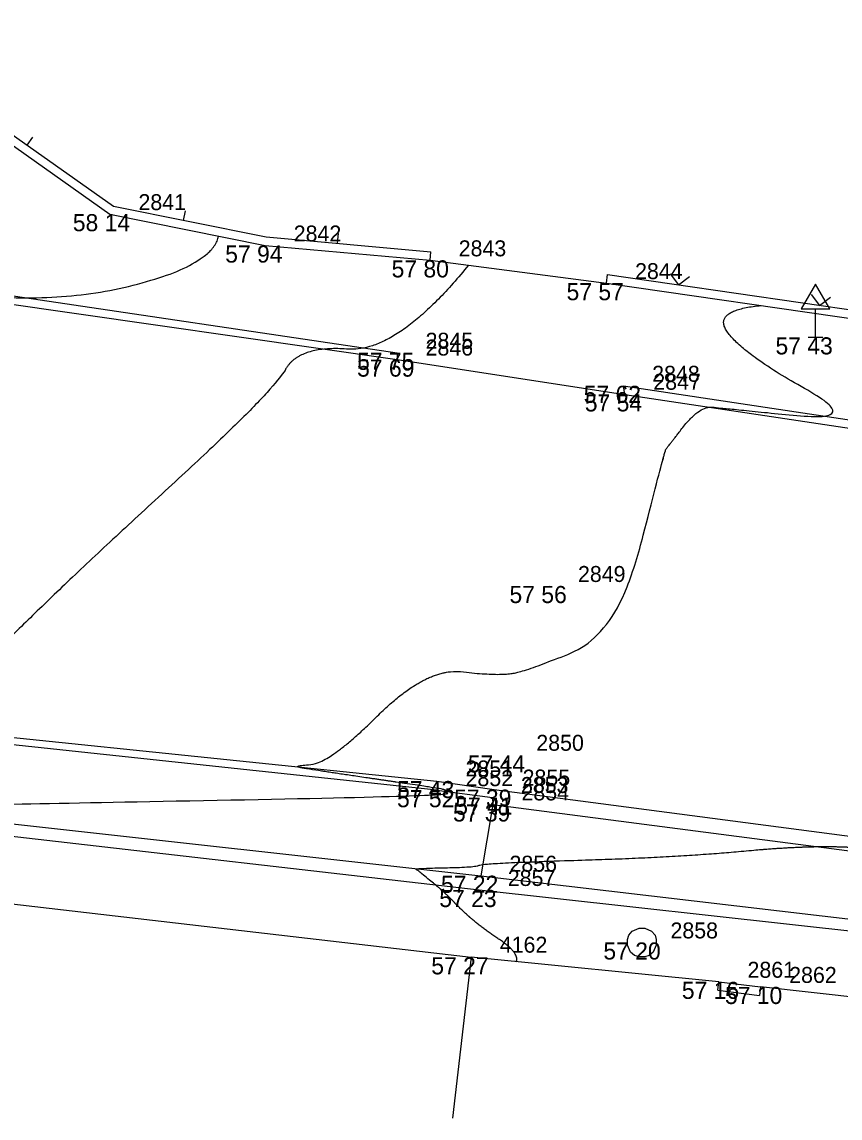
# Model space of a CAD drawing. Extents: x -704017 to -701500, y -1008977 to -1008450.
# Drawn here: x -702493.14 to -702478.81, y -1008778.35 to -1008759.13 of the extents above; entities that cross this region are included whole.
import ezdxf

# ---------------------------------------------------------------- set-up
doc = ezdxf.new("R2010")
doc.units = 0
for name, color, linetype in [('Z_body', 7, 'Continuous'), ('Z_body_cisla', 7, 'Continuous'), ('Z_body_vysky', 7, 'Continuous'), ('Z_budovy', 7, 'Continuous'), ('Z_chodnik', 7, 'Continuous'), ('Z_dopravni_znaceni', 7, 'Continuous'), ('Z_komunikace', 7, 'Continuous'), ('Z_obruby', 7, 'Continuous'), ('Z_oploceni', 7, 'Continuous'), ('Z_rozhrani_ploch', 7, 'Continuous'), ('Z_site_znaky_kanalizace', 7, 'Continuous'), ('Z_vrstevnice_hlavni', 7, 'Continuous'), ('Z_vrstevnice_vedlejsi', 7, 'Continuous'), ('Z_vstupy', 7, 'Continuous')]:
    doc.layers.add(name, color=color, linetype=linetype)

# ---------------------------------------------------------------- blocks, each defined once
blk = doc.blocks.new('POINT_DISPLAY')
blk.add_line((0, 0), (0, 0))
blk = doc.blocks.new('Z210')
blk.add_line((0, 0), (0, 0.17))
blk = doc.blocks.new('Z212')
for p, q in [((-0.17, 0.17), (0, 0)), ((0, 0), (0.17, 0.17))]:
    blk.add_line(p, q)
blk = doc.blocks.new('Z527')
for p, q in [((0, 0.93), (-0.25, 0.5)), ((0.25, 0.5), (0, 0.93)), ((-0.25, 0.5), (0.25, 0.5)), ((0, 0), (0, 0.5)), ((-0.13, 0), (0.13, 0))]:
    blk.add_line(p, q)
blk = doc.blocks.new('Z620')
for p, q in [((-0.23, 0.13), (-0.17, 0.2)), ((-0.17, 0.2), (-0.05, 0.25)), ((-0.05, 0.25), (0.05, 0.25)), ((0.05, 0.25), (0.17, 0.2)), ((0.17, 0.2), (0.23, 0.13)), ((-0.25, 0.05), (-0.23, 0.13)), ((-0.25, -0.05), (-0.25, 0.05)), ((0.23, 0.13), (0.25, 0.05)), ((0.25, 0.05), (0.25, -0.05)), ((-0.2, -0.17), (-0.25, -0.05)), ((-0.13, -0.23), (-0.2, -0.17)), ((0.2, -0.17), (0.13, -0.23)), ((0.25, -0.05), (0.2, -0.17)), ((-0.05, -0.25), (-0.13, -0.23)), ((0.05, -0.25), (-0.05, -0.25)), ((0.13, -0.23), (0.05, -0.25))]:
    blk.add_line(p, q)

msp = doc.modelspace()

# ---------------------------------------------------------------- linework, layer by layer
at = {"layer": 'Z_budovy'}
for p, q in [((-702495.22, -1008774.37), (-702485.27, -1008775.53)), ((-702485.27, -1008775.53), (-702485.6, -1008778.35))]:
    msp.add_line(p, q, dxfattribs=at)
at = {"layer": 'Z_chodnik'}
for p, q in [((-702495.54, -1008773.15), (-702485.13, -1008774.35)), ((-702485.13, -1008774.35), (-702477.28, -1008775.22))]:
    msp.add_line(p, q, dxfattribs=at)
at = {"layer": 'Z_komunikace'}
for p, q in [((-702495.43, -1008763.78), (-702486.57, -1008765.05)), ((-702486.57, -1008765.05), (-702482.58, -1008765.66)), ((-702482.58, -1008765.66), (-702468.75, -1008767.75)), ((-702495.38, -1008771.46), (-702485.87, -1008772.44)), ((-702485.87, -1008772.44), (-702484.87, -1008772.59)), ((-702484.87, -1008772.59), (-702477.01, -1008773.62))]:
    msp.add_line(p, q, dxfattribs=at)
at = {"layer": 'Z_obruby'}
for p, q in [((-702495.41, -1008763.62), (-702486.57, -1008764.93)), ((-702486.57, -1008764.93), (-702486.57, -1008765.05)), ((-702482.58, -1008765.66), (-702482.6, -1008765.51)), ((-702482.6, -1008765.51), (-702468.85, -1008767.59)), ((-702485.87, -1008772.6), (-702495.39, -1008771.58)), ((-702485.87, -1008772.6), (-702484.9, -1008772.73)), ((-702484.9, -1008772.73), (-702484.89, -1008772.85)), ((-702484.89, -1008772.85), (-702477.05, -1008773.87))]:
    msp.add_line(p, q, dxfattribs=at)
at = {"layer": 'Z_oploceni'}
for p, q in [((-702496.11, -1008759.13), (-702491.54, -1008762.36)), ((-702496.2, -1008759.25), (-702491.6, -1008762.5)), ((-702491.54, -1008762.36), (-702488.86, -1008762.9)), ((-702491.6, -1008762.5), (-702488.88, -1008763.05)), ((-702488.86, -1008762.9), (-702485.98, -1008763.16)), ((-702488.88, -1008763.05), (-702485.99, -1008763.31)), ((-702485.99, -1008763.31), (-702485.98, -1008763.16)), ((-702482.9, -1008763.71), (-702482.88, -1008763.56)), ((-702482.88, -1008763.56), (-702468.55, -1008765.63)), ((-702482.9, -1008763.71), (-702468.57, -1008765.78)), ((-702480.95, -1008776.11), (-702480.93, -1008775.96)), ((-702480.95, -1008776.11), (-702480.22, -1008776.2)), ((-702480.93, -1008775.96), (-702480.2, -1008776.05)), ((-702480.2, -1008776.05), (-702480.22, -1008776.2))]:
    msp.add_line(p, q, dxfattribs=at)
at = {"layer": 'Z_rozhrani_ploch'}
for p, q in [((-702495.54, -1008772.94), (-702485.1, -1008774.1)), ((-702484.89, -1008772.85), (-702485.1, -1008774.1)), ((-702485.1, -1008774.1), (-702477.22, -1008775.03))]:
    msp.add_line(p, q, dxfattribs=at)
at = {"layer": 'Z_vrstevnice_hlavni'}
msp.add_open_spline([(-702510.173, -1008772.658), (-702510.714, -1008772.203), (-702511.484, -1008771.252), (-702511.319, -1008771.123), (-702511.199, -1008771.066), (-702508.725, -1008770.905), (-702508.579, -1008770.878), (-702507.701, -1008770.748), (-702507.528, -1008770.584), (-702505.643, -1008770.573), (-702505.563, -1008770.58), (-702505.541, -1008770.602), (-702504.772, -1008770.664), (-702502.568, -1008770.251), (-702502.295, -1008770.203), (-702501.897, -1008770.153), (-702498.702, -1008767.51), (-702496.853, -1008766.543), (-702495.43, -1008763.78), (-702492.386, -1008764.068), (-702489.794, -1008763.372), (-702489.696, -1008762.885)], degree=2, dxfattribs=at)
at = {"layer": 'Z_vrstevnice_vedlejsi'}
for points in [[(-702485.318, -1008763.397), (-702486.57, -1008764.93), (-702488.285, -1008764.804), (-702488.762, -1008765.638), (-702492.37, -1008768.95), (-702494.464, -1008771.032), (-702495.307, -1008771.087), (-702496.276, -1008771.119), (-702497.81, -1008771.23)], [(-702493.746, -1008774.542), (-702493.918, -1008774.367), (-702495.54, -1008773.15), (-702495.838, -1008772.906), (-702495.627, -1008772.88), (-702495.54, -1008772.888), (-702495.534, -1008772.883), (-702492.317, -1008772.827), (-702485.819, -1008772.7), (-702485.719, -1008772.638), (-702485.694, -1008772.624), (-702485.716, -1008772.598), (-702485.87, -1008772.564), (-702488.091, -1008772.239), (-702488.43, -1008772.176), (-702487.75, -1008772.132), (-702486.058, -1008770.45), (-702484.809, -1008770.598), (-702484.265, -1008770.505), (-702482.684, -1008769.832), (-702481.884, -1008766.655), (-702481.829, -1008766.582), (-702481.263, -1008765.859), (-702480.808, -1008765.909), (-702478.369, -1008766.15), (-702480.478, -1008764.973), (-702481.07, -1008764.185), (-702480.189, -1008764.102)], [(-702484.481, -1008775.608), (-702484.416, -1008775.456), (-702485.2, -1008774.94), (-702485.781, -1008774.351), (-702485.901, -1008774.261), (-702486.219, -1008773.998), (-702486.26, -1008773.971), (-702485.177, -1008773.95), (-702485.063, -1008773.879), (-702481.636, -1008773.775), (-702479.402, -1008773.564), (-702478.013, -1008773.629), (-702478.401, -1008773.484), (-702478.397, -1008773.438), (-702478.049, -1008773.398), (-702477.618, -1008773.214), (-702477.532, -1008772.874), (-702477.136, -1008772.347), (-702473.031, -1008767.103), (-702469.736, -1008767.465), (-702469.555, -1008767.483), (-702469.889, -1008767.297), (-702470.89, -1008765.537), (-702470.506, -1008765.5)]]:
    msp.add_open_spline(points, degree=2, dxfattribs=at)
at = {"layer": 'Z_vstupy'}
for p, q in [((-702485.99, -1008763.31), (-702482.9, -1008763.71)), ((-702480.93, -1008775.96), (-702485.27, -1008775.53)), ((-702477.45, -1008776.36), (-702480.2, -1008776.05))]:
    msp.add_line(p, q, dxfattribs=at)

# ---------------------------------------------------------------- block references
at = {"layer": 'Z_body'}
for p in [(-702491.6, -1008762.5), (-702488.88, -1008763.05), (-702485.99, -1008763.31), (-702482.9, -1008763.71), (-702479.24, -1008764.66), (-702486.57, -1008764.93), (-702486.57, -1008765.05), (-702482.6, -1008765.51), (-702482.58, -1008765.66), (-702483.9, -1008769.02), (-702484.63, -1008771.99), (-702485.87, -1008772.44), (-702485.87, -1008772.6), (-702484.87, -1008772.59), (-702484.9, -1008772.73), (-702484.89, -1008772.85), (-702485.1, -1008774.1), (-702485.13, -1008774.35), (-702482.28, -1008775.27), (-702485.27, -1008775.53), (-702480.93, -1008775.96), (-702480.2, -1008776.05)]:
    msp.add_blockref('POINT_DISPLAY', p, dxfattribs=at)
at = {"layer": 'Z_dopravni_znaceni'}
msp.add_blockref('Z527', (-702479.24, -1008764.66), dxfattribs=at)
at = {"layer": 'Z_oploceni'}
for name, p, rotation in [('Z210', (-702493.05, -1008761.29), -35.20000000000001), ('Z210', (-702490.31, -1008762.61), -11.399999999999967), ('Z210', (-702487.61, -1008763.01), -5.100000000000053), ('Z212', (-702481.64, -1008763.74), -8.200000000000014), ('Z212', (-702479.17, -1008764.1), -8.200000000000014)]:
    msp.add_blockref(name, p, dxfattribs=dict(at, rotation=rotation))
at = {"layer": 'Z_site_znaky_kanalizace'}
msp.add_blockref('Z620', (-702482.28, -1008775.27), dxfattribs=at)

# ---------------------------------------------------------------- texts
at = {"layer": 'Z_body_cisla'}
for s, p in [('2841', (-702491.1, -1008762.43)), ('2842', (-702488.38, -1008762.98)), ('2843', (-702485.49, -1008763.24)), ('2844', (-702482.4, -1008763.64)), ('2845', (-702486.07, -1008764.86)), ('2846', (-702486.07, -1008764.98)), ('2848', (-702482.1, -1008765.44)), ('2847', (-702482.08, -1008765.58)), ('2849', (-702483.4, -1008768.95)), ('2850', (-702484.13, -1008771.91)), ('2851', (-702485.37, -1008772.36)), ('2852', (-702485.37, -1008772.53)), ('2855', (-702484.37, -1008772.52)), ('2853', (-702484.4, -1008772.65)), ('2854', (-702484.39, -1008772.78)), ('2856', (-702484.6, -1008774.03)), ('2857', (-702484.63, -1008774.28)), ('2858', (-702481.78, -1008775.2)), ('4162', (-702484.77, -1008775.45)), ('2861', (-702480.43, -1008775.89)), ('2862', (-702479.7, -1008775.98))]:
    msp.add_text(s, height=0.28, dxfattribs=at).set_placement(p)
at = {"layer": 'Z_body_vysky'}
for s, p in [('58 14', (-702492.25, -1008762.8)), ('57 94', (-702489.58, -1008763.35)), ('57 80', (-702486.665, -1008763.61)), ('57 57', (-702483.6, -1008764.01)), ('57 43', (-702479.94, -1008764.96)), ('57 75', (-702487.27, -1008765.23)), ('57 69', (-702487.27, -1008765.35)), ('57 62', (-702483.3, -1008765.81)), ('57 54', (-702483.28, -1008765.96)), ('57 56', (-702484.6, -1008769.32)), ('57 44', (-702485.33, -1008772.29)), ('57 43', (-702486.57, -1008772.74)), ('57 52', (-702486.57, -1008772.9)), ('57 39', (-702485.57, -1008772.89)), ('57 39', (-702485.59, -1008773.15)), ('57 41', (-702485.55, -1008773.03)), ('57 22', (-702485.8, -1008774.4)), ('57 23', (-702485.83, -1008774.65)), ('57 20', (-702482.955, -1008775.57)), ('57 27', (-702485.97, -1008775.83)), ('57 16', (-702481.58, -1008776.26)), ('57 10', (-702480.825, -1008776.35))]:
    msp.add_text(s, height=0.3, dxfattribs=at).set_placement(p)

doc.saveas('drawing.dxf')
